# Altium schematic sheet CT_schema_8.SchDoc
size 391 x 238 mm
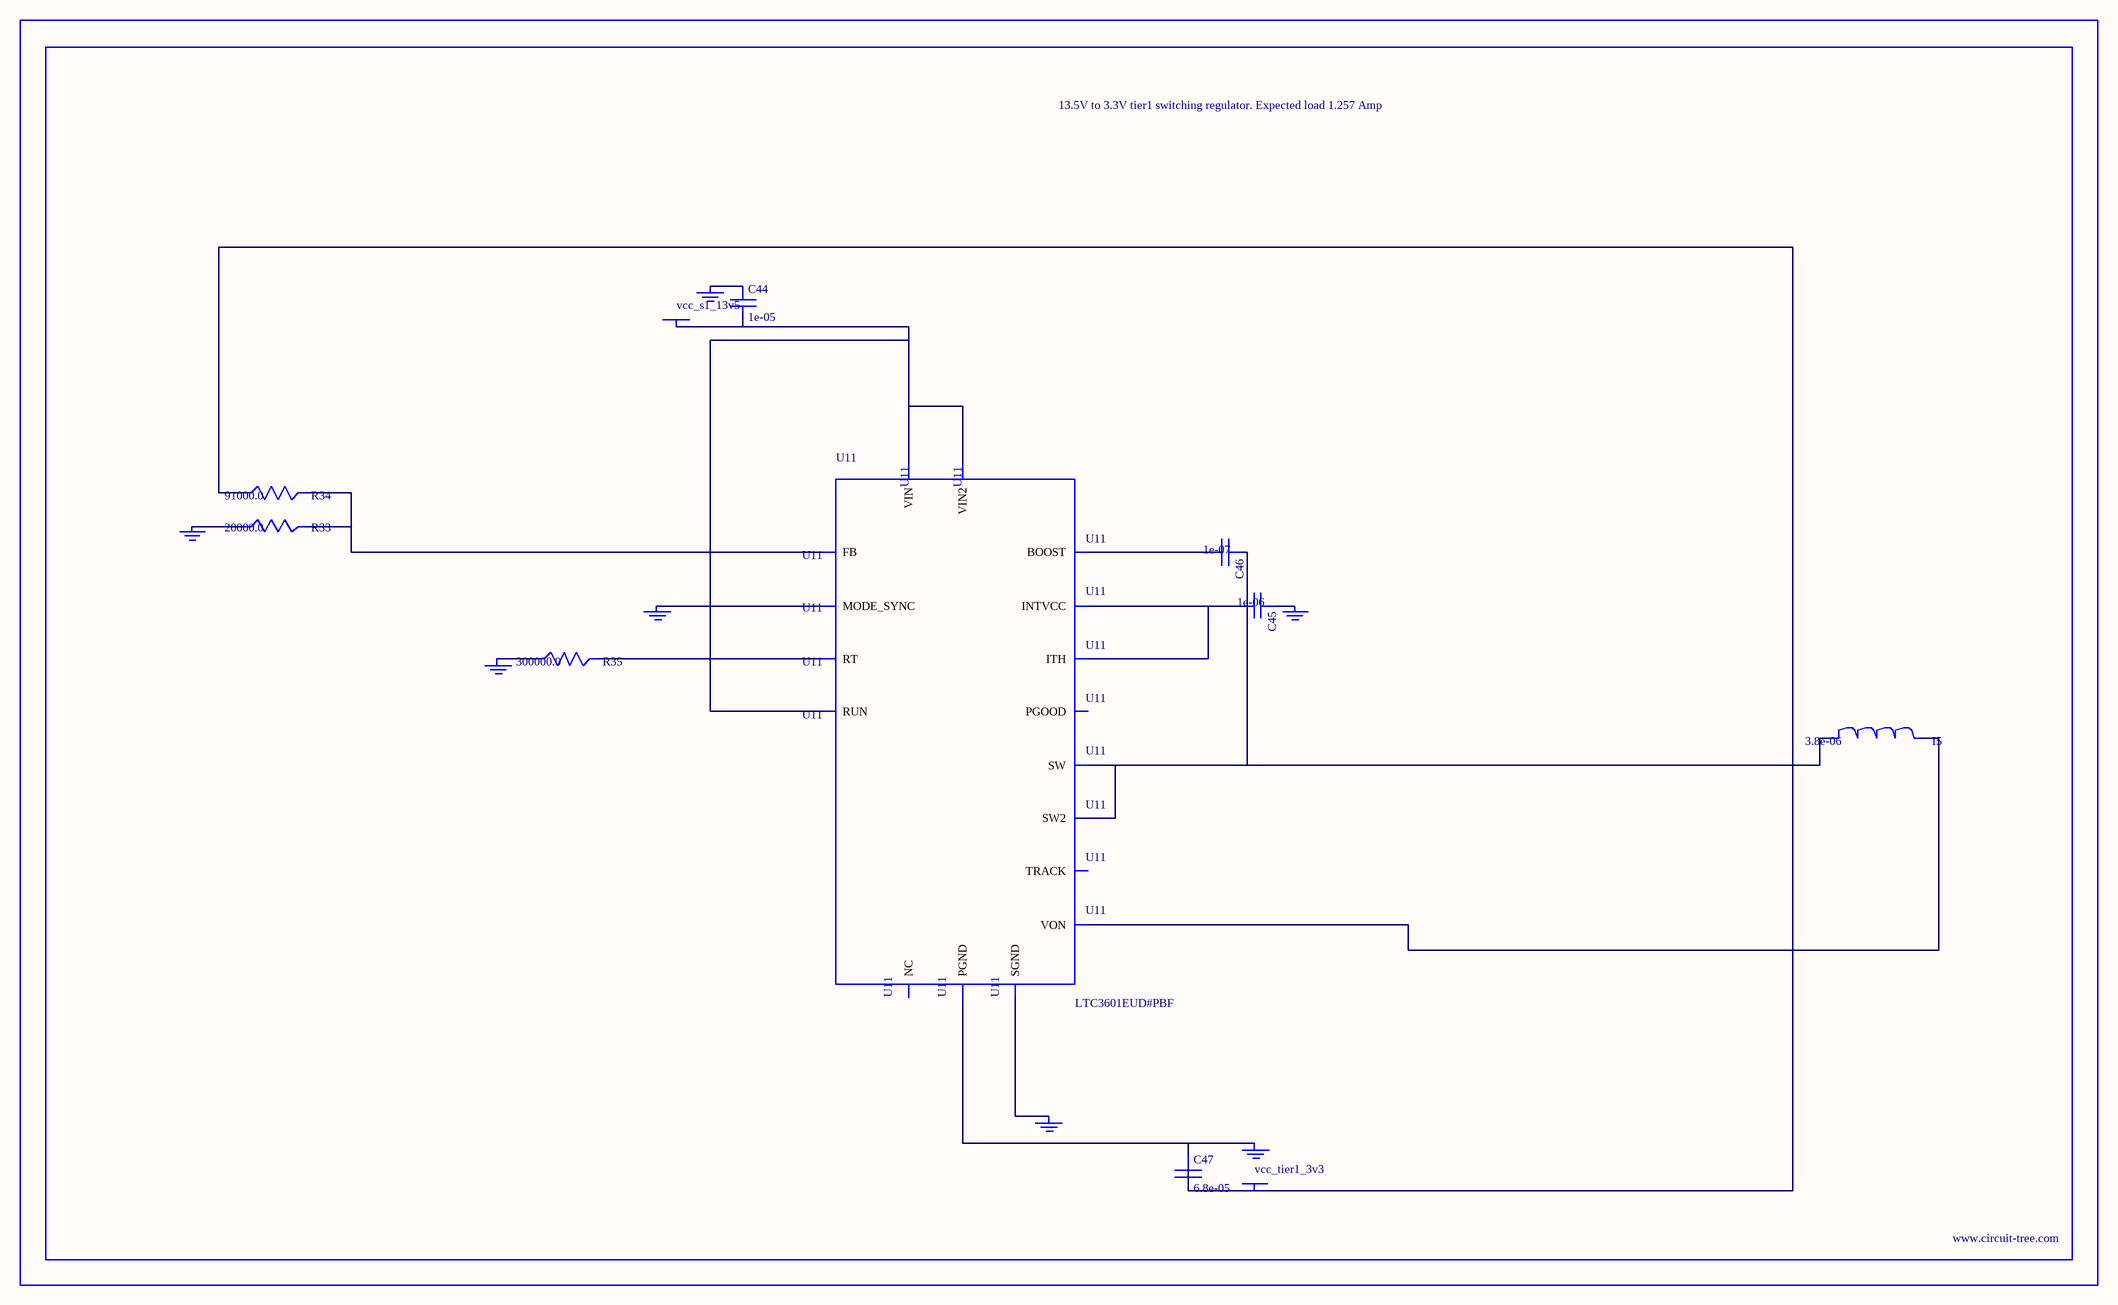
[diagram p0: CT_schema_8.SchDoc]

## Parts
BORDER7  (no value)
C44  1e-05  [C0805]
C45  1e-06  [C0603]
C46  1e-07  [C0402]
C47  6.8e-05  [2220]
GND_INSTANCE_7_0  (no value)
GND_INSTANCE_7_1  (no value)
GND_INSTANCE_7_2  (no value)
GND_INSTANCE_7_3  (no value)
GND_INSTANCE_7_4  (no value)
GND_INSTANCE_7_5  (no value)
GND_INSTANCE_7_6  (no value)
I5  3.8e-06  [DR1040]
POWER_INSTANCE_7_0  vcc_s1_13v5
POWER_INSTANCE_7_1  vcc_tier1_3v3
R33  20000.0  [R0603]
R34  91000.0  [R0603]
R35  300000.0  [R0603]
U11  LTC3601EUD#PBF  [QFN-16_EP]

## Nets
NetC44_1: C44.1 GND_INSTANCE_7_5.0(GND)
NetC44_2: C44.2 POWER_INSTANCE_7_0.0(PWR) U11.14(RUN) U11.15(VIN) U11.16(VIN2)
NetC45_1: C45.1 GND_INSTANCE_7_1.0(GND)
NetC45_2: C45.2 U11.7(INTVCC) U11.12(ITH)
NetC46_1: C46.1 I5.1 U11.3(SW) U11.4(SW2)
NetC46_2: C46.2 U11.6(BOOST)
NetC47_1: C47.1 GND_INSTANCE_7_6.0(GND) U11.17(PGND)
NetC47_2: C47.2 I5.2 POWER_INSTANCE_7_1.0(PWR) R34.1 U11.8(VON)
NetGND_INSTANCE_7_0_0: GND_INSTANCE_7_0.0(GND) U11.1(MODE_SYNC)
NetGND_INSTANCE_7_2_0: GND_INSTANCE_7_2.0(GND) U11.9(SGND)
NetGND_INSTANCE_7_3_0: GND_INSTANCE_7_3.0(GND) R35.1
NetGND_INSTANCE_7_4_0: GND_INSTANCE_7_4.0(GND) R33.1
NetR33_2: R33.2 R34.2 U11.11(FB)
NetR35_2: R35.2 U11.10(RT)

Not connected (* = marked no-connect by the designer): U11 2(PGOOD) 5(NC) 13(TRACK)

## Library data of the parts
BORDER7 = BORDER_PAGE7
C44 = C0805C106K8RACTU
C45 = C0603C105K3RACTU
C46 = C0402C104K3RACTU
C47 = C5750X5R1A686M
GND_INSTANCE_7_0-GND_INSTANCE_7_6 = GND
I5 = DR1040-3R8-R
POWER_INSTANCE_7_0 POWER_INSTANCE_7_1 = PWR
R33 = RC0603JR-0720KL
R34 = RC0603JR-0791KL
R35 = RC0603JR-07300KL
